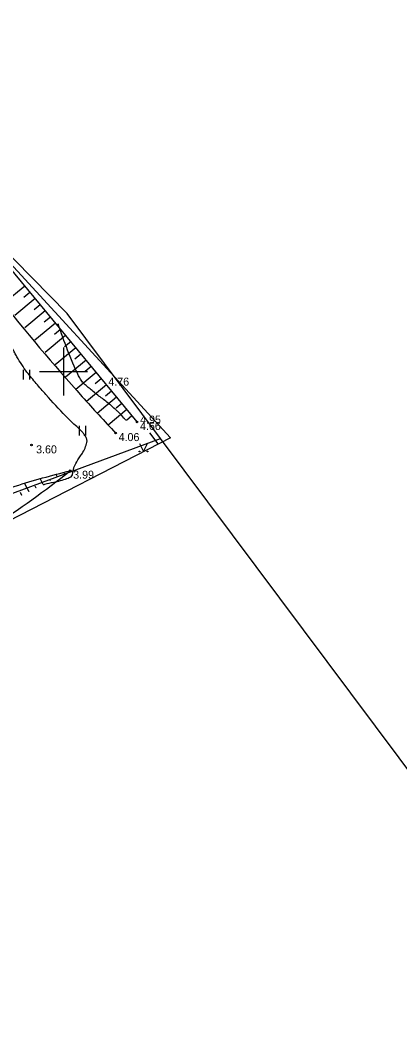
# Model space of a CAD drawing. Extents: x 519536 to 519949, y 326041 to 326519.
# Drawn here: x 519697.3 to 519721, y 326359.2 to 326421.9 of the extents above; entities that cross this region are included whole.
import ezdxf

# ---------------------------------------------------------------- set-up
doc = ezdxf.new("R2010")
doc.units = 0
for name, color, linetype in [('GEOD_ELEM_####_####_#', 7, 'Continuous'), ('NORB_ZOGS_KBST_####_#', 7, 'Continuous'), ('NORB_ZOGS_ZBET_####_#', 7, 'Continuous'), ('RAMI_UZMR_####_####_#', 7, 'Continuous'), ('RELJ_AATZ_####_TKST_#', 7, 'Continuous'), ('RELJ_ELEM_####_####_#', 7, 'Continuous'), ('RELJ_HORZ_PAMT_####_#', 7, 'Continuous'), ('RELJ_HORZ_RESN_####_#', 7, 'Continuous'), ('RELJ_NOGA_####_####_#', 7, 'Continuous'), ('RELJ_NOGL_####_####_#', 7, 'Continuous'), ('ROBZ_UZMR_####_####_#', 7, 'Continuous'), ('TERT_ELEM_####_####_#', 7, 'Continuous')]:
    doc.layers.add(name, color=color, linetype=linetype)

msp = doc.modelspace()

# ---------------------------------------------------------------- linework, layer by layer
at = {"layer": 'GEOD_ELEM_####_####_#'}
for p, q in [((519700, 326401.5), (519700, 326400)), ((519698.5, 326400), (519700, 326400)), ((519700, 326400), (519700, 326398.5)), ((519700, 326400), (519701.5, 326400))]:
    msp.add_line(p, q, dxfattribs=at)
at = {"layer": 'NORB_ZOGS_KBST_####_#'}
msp.add_lwpolyline([(519704.591, 326396.84), (519691.702, 326412.425)], dxfattribs=at)
at = {"layer": 'NORB_ZOGS_ZBET_####_#'}
msp.add_lwpolyline([(519705.917, 326395.468), (519705.398, 326396.158)], dxfattribs=at)
at = {"layer": 'RAMI_UZMR_####_####_#'}
msp.add_lwpolyline([(519606.503, 326354.123), (519598.183, 326371.842), (519589.598, 326374.981), (519581.568, 326396.559), (519571.96, 326403.209), (519550.477, 326420.838), (519546.03, 326425.168), (519546.311, 326425.748), (519562.267, 326424.735), (519567.537, 326424.176), (519622.695, 326420.6), (519656.101, 326418.428), (519678.291, 326416.771), (519682.862, 326421.74), (519706.678, 326395.86), (519695.81, 326390.264), (519680.586, 326385.663), (519636.229, 326369.014), (519636.521, 326358.648)], dxfattribs=at)
at = {"layer": 'RELJ_ELEM_####_####_#'}
for centre in [(519704.591, 326396.84), (519703.254, 326396.147), (519697.996, 326395.403), (519700.416, 326393.799)]:
    msp.add_circle(centre, 0.05, dxfattribs=at)
at = {"layer": 'RELJ_HORZ_PAMT_####_#'}
msp.add_spline([(519703.896, 326396.934), (519703.775, 326397.086), (519703.513, 326397.377), (519703.369, 326397.513), (519703.223, 326397.646), (519702.926, 326397.903), (519702.644, 326398.132), (519702.356, 326398.353), (519702.067, 326398.573), (519701.782, 326398.801), (519701.535, 326399.003), (519701.298, 326399.219), (519701.092, 326399.457), (519700.941, 326399.729), (519699.66, 326402.96)], degree=3, dxfattribs=at)
at = {"layer": 'RELJ_HORZ_RESN_####_#'}
msp.add_spline([(519698.726, 326392.928), (519698.835, 326392.956), (519699.387, 326393.081), (519700.212, 326393.312), (519700.348, 326393.365), (519700.482, 326393.424), (519700.553, 326393.541), (519700.577, 326393.647), (519700.598, 326393.752), (519700.618, 326393.858), (519700.643, 326393.962), (519700.652, 326393.992), (519700.893, 326394.479), (519700.969, 326394.602), (519701.051, 326394.72), (519701.134, 326394.839), (519701.212, 326394.964), (519701.379, 326395.301), (519701.436, 326395.476), (519701.469, 326395.653), (519701.452, 326395.76), (519701.411, 326395.865), (519701.356, 326395.96), (519701.296, 326396.052), (519701.16, 326396.221), (519700.831, 326396.549), (519700.475, 326396.868), (519700.14, 326397.197), (519698.898, 326398.547), (519698.295, 326399.242), (519698.001, 326399.597), (519697.714, 326399.959), (519697.09, 326400.915), (519696.951, 326401.164), (519696.818, 326401.415), (519696.58, 326401.93), (519696.193, 326402.912)], degree=3, dxfattribs=at)
at = {"layer": 'RELJ_NOGA_####_####_#'}
for p, q in [((519697.581, 326405.317), (519696.319, 326404.273)), ((519697.899, 326404.931), (519697.519, 326404.617)), ((519698.218, 326404.546), (519696.946, 326403.494)), ((519698.855, 326403.775), (519697.575, 326402.717)), ((519698.537, 326404.161), (519698.154, 326403.844)), ((519699.493, 326403.005), (519698.207, 326401.942)), ((519699.174, 326403.39), (519698.789, 326403.072)), ((519699.811, 326402.62), (519699.425, 326402.3)), ((519700.13, 326402.234), (519698.843, 326401.17)), ((519700.449, 326401.849), (519700.063, 326401.53)), ((519700.767, 326401.464), (519699.482, 326400.401)), ((519701.086, 326401.078), (519700.701, 326400.76)), ((519701.404, 326400.693), (519700.126, 326399.635)), ((519702.042, 326399.922), (519700.774, 326398.874)), ((519701.723, 326400.308), (519701.341, 326399.992)), ((519702.36, 326399.537), (519701.982, 326399.224)), ((519702.679, 326399.152), (519701.43, 326398.119)), ((519702.998, 326398.767), (519702.628, 326398.461)), ((519703.316, 326398.381), (519702.105, 326397.379)), ((519703.635, 326397.996), (519703.279, 326397.701)), ((519703.954, 326397.611), (519702.789, 326396.647)), ((519704.272, 326397.225), (519703.93, 326396.942)), ((519704.591, 326396.84), (519704.59, 326396.839)), ((519699.622, 326393.39), (519699.533, 326393.562)), ((519700.066, 326393.619), (519700.055, 326393.641)), ((519700.066, 326393.619), (519700.066, 326393.619)), ((519697.844, 326392.474), (519697.561, 326393.022)), ((519698.733, 326392.932), (519698.542, 326393.302)), ((519698.733, 326392.932), (519698.732, 326392.933)), ((519699.177, 326393.161), (519699.135, 326393.242)), ((519699.177, 326393.161), (519699.177, 326393.161)), ((519699.622, 326393.39), (519699.621, 326393.391)), ((519697.399, 326392.245), (519697.303, 326392.431)), ((519697.844, 326392.474), (519697.843, 326392.475)), ((519698.288, 326392.703), (519698.217, 326392.842)), ((519698.288, 326392.703), (519698.288, 326392.703)), ((519697.399, 326392.245), (519697.399, 326392.245))]:
    msp.add_line(p, q, dxfattribs=at)
msp.add_spline([(519633.005, 326382.956), (519639.907, 326381.113), (519643.418, 326377.883), (519651.003, 326389.626), (519657.231, 326401.681), (519665.468, 326403.519), (519679.321, 326396.739), (519683.853, 326390.018), (519690.141, 326388.505), (519700.416, 326393.799)], degree=3, dxfattribs=at)
at = {"layer": 'RELJ_NOGL_####_####_#'}
for points in [[(519690.926, 326411.003), (519701.164, 326398.42), (519703.254, 326396.147)], [(519691.184, 326390.387), (519696.984, 326392.832), (519700.416, 326393.799)]]:
    msp.add_spline(points, degree=3, dxfattribs=at)
at = {"layer": 'ROBZ_UZMR_####_####_#'}
for p, q in [((519700.236, 326403.605), (519683.072, 326421.021)), ((519706.067, 326395.801), (519700.236, 326403.605)), ((519634.774, 326369.546), (519706.067, 326395.801)), ((519726.673, 326368.224), (519706.067, 326395.801))]:
    msp.add_line(p, q, dxfattribs=at)
at = {"layer": 'TERT_ELEM_####_####_#'}
for p, q in [((519697.5, 326399.5), (519697.5, 326400.1)), ((519697.9, 326399.5), (519697.9, 326400.1)), ((519701, 326396), (519701, 326396.6)), ((519701.4, 326396), (519701.4, 326396.6)), ((519704.75, 326395.5), (519705, 326395)), ((519705, 326395), (519705.25, 326395.5))]:
    msp.add_line(p, q, dxfattribs=at)
for centre, radius in [((519704.75, 326395), 0.028), ((519705.25, 326395), 0.0263)]:
    msp.add_circle(centre, radius, dxfattribs=at)

# ---------------------------------------------------------------- texts
at = {"layer": 'RELJ_AATZ_####_TKST_#'}
for s, p in [(' 4.76', (519702.613, 326399.11)), (' 4.66', (519704.591, 326396.34)), (' 4.95', (519704.601, 326396.738)), (' 4.06', (519703.254, 326395.647)), ('3.60', (519698.284, 326394.88)), (' 3.99', (519700.416, 326393.299))]:
    msp.add_text(s, height=0.5, dxfattribs=at).set_placement(p)

doc.saveas('drawing.dxf')
